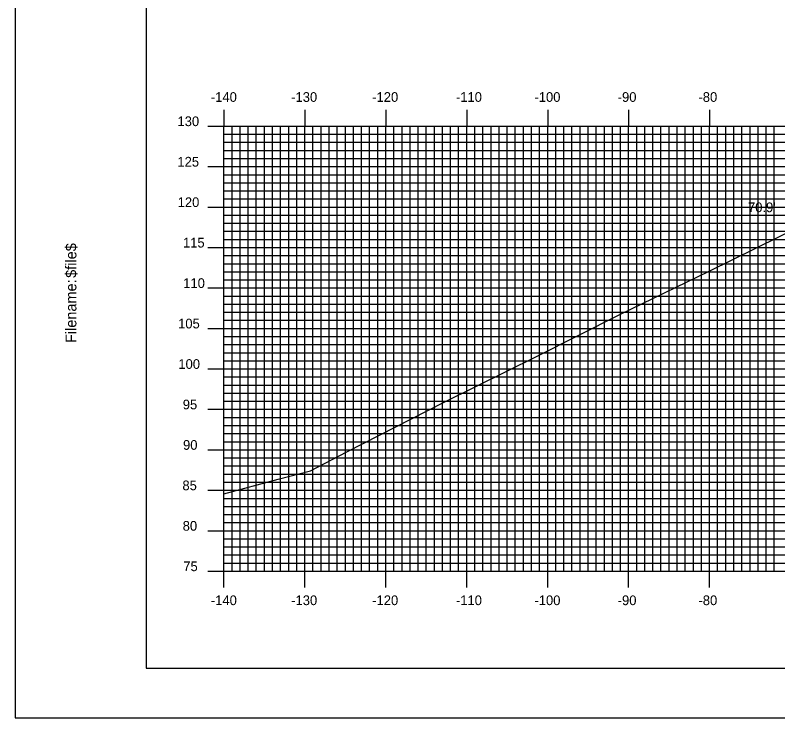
# Model space of a CAD drawing. Extents: x 1684012 to 1684355, y 461260 to 461480.
# Drawn here: x 1684011.9 to 1684106.1, y 461260 to 461346.8 of the extents above; entities that cross this region are included whole.
import ezdxf

# ---------------------------------------------------------------- set-up
doc = ezdxf.new("R2010")
doc.units = 0
for name, color, linetype in [('BORDER', 7, 'Continuous'), ('D_Text_Standard', 7, 'Continuous'), ('H_V ANNOTATION', 7, 'Continuous'), ('MAJOR', 7, 'Continuous'), ('MINOR', 7, 'Continuous'), ('PLOT BOUNDARY', 7, 'Continuous'), ('S_Roadway_Centerline', 7, 'Continuous')]:
    doc.layers.add(name, color=color, linetype=linetype)

msp = doc.modelspace()

# ---------------------------------------------------------------- linework, layer by layer
at = {"layer": 'BORDER'}
msp.add_lwpolyline([(1684028.09, 461266.072), (1684348.09, 461266.072), (1684348.09, 461476.072), (1684028.09, 461476.072)], close=True, dxfattribs=at)
at = {"layer": 'MAJOR'}
for p, q in [((1684037.69, 461335.076), (1684037.69, 461333.072)), ((1684047.69, 461335.076), (1684047.69, 461333.072)), ((1684057.69, 461335.076), (1684057.69, 461333.072)), ((1684067.69, 461335.076), (1684067.69, 461333.072)), ((1684077.69, 461335.076), (1684077.69, 461333.072)), ((1684087.69, 461335.076), (1684087.69, 461333.072)), ((1684097.69, 461335.076), (1684097.69, 461333.072)), ((1684035.686, 461333.072), (1684037.69, 461333.072)), ((1684037.69, 461333.072), (1684317.69, 461333.072)), ((1684037.69, 461278.072), (1684037.69, 461333.072)), ((1684037.69, 461278.072), (1684037.69, 461333.072)), ((1684037.69, 461333.072), (1684317.69, 461333.072)), ((1684047.69, 461278.072), (1684047.69, 461333.072)), ((1684057.69, 461278.072), (1684057.69, 461333.072)), ((1684067.69, 461278.072), (1684067.69, 461333.072)), ((1684077.69, 461278.072), (1684077.69, 461333.072)), ((1684087.69, 461278.072), (1684087.69, 461333.072)), ((1684097.69, 461278.072), (1684097.69, 461333.072)), ((1684035.686, 461328.072), (1684037.69, 461328.072)), ((1684037.69, 461328.072), (1684317.69, 461328.072)), ((1684035.686, 461323.072), (1684037.69, 461323.072)), ((1684037.69, 461323.072), (1684317.69, 461323.072)), ((1684035.686, 461318.072), (1684037.69, 461318.072)), ((1684037.69, 461318.072), (1684317.69, 461318.072)), ((1684035.686, 461313.072), (1684037.69, 461313.072)), ((1684037.69, 461313.072), (1684317.69, 461313.072)), ((1684035.686, 461308.072), (1684037.69, 461308.072)), ((1684037.69, 461308.072), (1684317.69, 461308.072)), ((1684035.686, 461303.072), (1684037.69, 461303.072)), ((1684037.69, 461303.072), (1684317.69, 461303.072)), ((1684035.686, 461298.072), (1684037.69, 461298.072)), ((1684037.69, 461298.072), (1684317.69, 461298.072)), ((1684035.686, 461293.072), (1684037.69, 461293.072)), ((1684037.69, 461293.072), (1684317.69, 461293.072)), ((1684035.686, 461288.072), (1684037.69, 461288.072)), ((1684037.69, 461288.072), (1684317.69, 461288.072)), ((1684035.686, 461283.072), (1684037.69, 461283.072)), ((1684037.69, 461283.072), (1684317.69, 461283.072)), ((1684035.686, 461278.072), (1684037.69, 461278.072)), ((1684037.69, 461278.072), (1684317.69, 461278.072)), ((1684037.69, 461278.072), (1684317.69, 461278.072)), ((1684037.69, 461276.068), (1684037.69, 461278.072)), ((1684047.69, 461276.068), (1684047.69, 461278.072)), ((1684057.69, 461276.068), (1684057.69, 461278.072)), ((1684067.69, 461276.068), (1684067.69, 461278.072)), ((1684077.69, 461276.068), (1684077.69, 461278.072)), ((1684087.69, 461276.068), (1684087.69, 461278.072)), ((1684097.69, 461276.068), (1684097.69, 461278.072))]:
    msp.add_line(p, q, dxfattribs=at)
at = {"layer": 'MINOR'}
for p, q in [((1684038.69, 461278.072), (1684038.69, 461333.072)), ((1684039.69, 461278.072), (1684039.69, 461333.072)), ((1684040.69, 461278.072), (1684040.69, 461333.072)), ((1684041.69, 461278.072), (1684041.69, 461333.072)), ((1684042.69, 461278.072), (1684042.69, 461333.072)), ((1684043.69, 461278.072), (1684043.69, 461333.072)), ((1684044.69, 461278.072), (1684044.69, 461333.072)), ((1684045.69, 461278.072), (1684045.69, 461333.072)), ((1684046.69, 461278.072), (1684046.69, 461333.072)), ((1684048.69, 461278.072), (1684048.69, 461333.072)), ((1684049.69, 461278.072), (1684049.69, 461333.072)), ((1684050.69, 461278.072), (1684050.69, 461333.072)), ((1684051.69, 461278.072), (1684051.69, 461333.072)), ((1684052.69, 461278.072), (1684052.69, 461333.072)), ((1684053.69, 461278.072), (1684053.69, 461333.072)), ((1684054.69, 461278.072), (1684054.69, 461333.072)), ((1684055.69, 461278.072), (1684055.69, 461333.072)), ((1684056.69, 461278.072), (1684056.69, 461333.072)), ((1684058.69, 461278.072), (1684058.69, 461333.072)), ((1684059.69, 461278.072), (1684059.69, 461333.072)), ((1684060.69, 461278.072), (1684060.69, 461333.072)), ((1684061.69, 461278.072), (1684061.69, 461333.072)), ((1684062.69, 461278.072), (1684062.69, 461333.072)), ((1684063.69, 461278.072), (1684063.69, 461333.072)), ((1684064.69, 461278.072), (1684064.69, 461333.072)), ((1684065.69, 461278.072), (1684065.69, 461333.072)), ((1684066.69, 461278.072), (1684066.69, 461333.072)), ((1684068.69, 461278.072), (1684068.69, 461333.072)), ((1684069.69, 461278.072), (1684069.69, 461333.072)), ((1684070.69, 461278.072), (1684070.69, 461333.072)), ((1684071.69, 461278.072), (1684071.69, 461333.072)), ((1684072.69, 461278.072), (1684072.69, 461333.072)), ((1684073.69, 461278.072), (1684073.69, 461333.072)), ((1684074.69, 461278.072), (1684074.69, 461333.072)), ((1684075.69, 461278.072), (1684075.69, 461333.072)), ((1684076.69, 461278.072), (1684076.69, 461333.072)), ((1684078.69, 461278.072), (1684078.69, 461333.072)), ((1684079.69, 461278.072), (1684079.69, 461333.072)), ((1684080.69, 461278.072), (1684080.69, 461333.072)), ((1684081.69, 461278.072), (1684081.69, 461333.072)), ((1684082.69, 461278.072), (1684082.69, 461333.072)), ((1684083.69, 461278.072), (1684083.69, 461333.072)), ((1684084.69, 461278.072), (1684084.69, 461333.072)), ((1684085.69, 461278.072), (1684085.69, 461333.072)), ((1684086.69, 461278.072), (1684086.69, 461333.072)), ((1684088.69, 461278.072), (1684088.69, 461333.072)), ((1684089.69, 461278.072), (1684089.69, 461333.072)), ((1684090.69, 461278.072), (1684090.69, 461333.072)), ((1684091.69, 461278.072), (1684091.69, 461333.072)), ((1684092.69, 461278.072), (1684092.69, 461333.072)), ((1684093.69, 461278.072), (1684093.69, 461333.072)), ((1684094.69, 461278.072), (1684094.69, 461333.072)), ((1684095.69, 461278.072), (1684095.69, 461333.072)), ((1684096.69, 461278.072), (1684096.69, 461333.072)), ((1684098.69, 461278.072), (1684098.69, 461333.072)), ((1684099.69, 461278.072), (1684099.69, 461333.072)), ((1684100.69, 461278.072), (1684100.69, 461333.072)), ((1684101.69, 461278.072), (1684101.69, 461333.072)), ((1684102.69, 461278.072), (1684102.69, 461333.072)), ((1684103.69, 461278.072), (1684103.69, 461333.072)), ((1684104.69, 461278.072), (1684104.69, 461333.072)), ((1684105.69, 461278.072), (1684105.69, 461333.072)), ((1684037.69, 461332.072), (1684317.69, 461332.072)), ((1684037.69, 461332.072), (1684039.694, 461332.072)), ((1684037.69, 461331.072), (1684317.69, 461331.072)), ((1684037.69, 461331.072), (1684039.694, 461331.072)), ((1684037.69, 461330.072), (1684317.69, 461330.072)), ((1684037.69, 461330.072), (1684039.694, 461330.072)), ((1684037.69, 461329.072), (1684317.69, 461329.072)), ((1684037.69, 461329.072), (1684039.694, 461329.072)), ((1684037.69, 461327.072), (1684317.69, 461327.072)), ((1684037.69, 461327.072), (1684039.694, 461327.072)), ((1684037.69, 461326.072), (1684317.69, 461326.072)), ((1684037.69, 461326.072), (1684039.694, 461326.072)), ((1684037.69, 461325.072), (1684317.69, 461325.072)), ((1684037.69, 461325.072), (1684039.694, 461325.072)), ((1684037.69, 461324.072), (1684317.69, 461324.072)), ((1684037.69, 461324.072), (1684039.694, 461324.072)), ((1684037.69, 461322.072), (1684317.69, 461322.072)), ((1684037.69, 461322.072), (1684039.694, 461322.072)), ((1684037.69, 461321.072), (1684037.69, 461321.072)), ((1684037.69, 461321.072), (1684039.694, 461321.072)), ((1684037.69, 461321.072), (1684317.69, 461321.072)), ((1684037.69, 461320.072), (1684317.69, 461320.072)), ((1684037.69, 461320.072), (1684039.694, 461320.072)), ((1684037.69, 461319.072), (1684317.69, 461319.072)), ((1684037.69, 461319.072), (1684039.694, 461319.072)), ((1684037.69, 461317.072), (1684317.69, 461317.072)), ((1684037.69, 461317.072), (1684039.694, 461317.072)), ((1684037.69, 461316.072), (1684317.69, 461316.072)), ((1684037.69, 461316.072), (1684039.694, 461316.072)), ((1684037.69, 461315.072), (1684317.69, 461315.072)), ((1684037.69, 461315.072), (1684039.694, 461315.072)), ((1684037.69, 461314.072), (1684317.69, 461314.072)), ((1684037.69, 461314.072), (1684039.694, 461314.072)), ((1684037.69, 461312.072), (1684317.69, 461312.072)), ((1684037.69, 461312.072), (1684039.694, 461312.072)), ((1684037.69, 461311.072), (1684317.69, 461311.072)), ((1684037.69, 461311.072), (1684039.694, 461311.072)), ((1684037.69, 461310.072), (1684317.69, 461310.072)), ((1684037.69, 461310.072), (1684039.694, 461310.072)), ((1684037.69, 461309.072), (1684317.69, 461309.072)), ((1684037.69, 461309.072), (1684039.694, 461309.072)), ((1684037.69, 461307.072), (1684317.69, 461307.072)), ((1684037.69, 461307.072), (1684039.694, 461307.072)), ((1684037.69, 461306.072), (1684317.69, 461306.072)), ((1684037.69, 461306.072), (1684039.694, 461306.072)), ((1684037.69, 461305.072), (1684317.69, 461305.072)), ((1684037.69, 461305.072), (1684039.694, 461305.072)), ((1684037.69, 461304.072), (1684317.69, 461304.072)), ((1684037.69, 461304.072), (1684039.694, 461304.072)), ((1684037.69, 461302.072), (1684317.69, 461302.072)), ((1684037.69, 461302.072), (1684039.694, 461302.072)), ((1684037.69, 461301.072), (1684317.69, 461301.072)), ((1684037.69, 461301.072), (1684039.694, 461301.072)), ((1684037.69, 461300.072), (1684317.69, 461300.072)), ((1684037.69, 461300.072), (1684039.694, 461300.072)), ((1684037.69, 461299.072), (1684317.69, 461299.072)), ((1684037.69, 461299.072), (1684039.694, 461299.072)), ((1684037.69, 461297.072), (1684317.69, 461297.072)), ((1684037.69, 461297.072), (1684039.694, 461297.072)), ((1684037.69, 461296.072), (1684317.69, 461296.072)), ((1684037.69, 461296.072), (1684039.694, 461296.072)), ((1684037.69, 461295.072), (1684317.69, 461295.072)), ((1684037.69, 461295.072), (1684039.694, 461295.072)), ((1684037.69, 461294.072), (1684317.69, 461294.072)), ((1684037.69, 461294.072), (1684039.694, 461294.072)), ((1684037.69, 461292.072), (1684317.69, 461292.072)), ((1684037.69, 461292.072), (1684039.694, 461292.072)), ((1684037.69, 461291.072), (1684317.69, 461291.072)), ((1684037.69, 461291.072), (1684039.694, 461291.072)), ((1684037.69, 461290.072), (1684317.69, 461290.072)), ((1684037.69, 461290.072), (1684039.694, 461290.072)), ((1684037.69, 461289.072), (1684317.69, 461289.072)), ((1684037.69, 461289.072), (1684039.694, 461289.072)), ((1684037.69, 461287.072), (1684317.69, 461287.072)), ((1684037.69, 461287.072), (1684039.694, 461287.072)), ((1684037.69, 461286.072), (1684317.69, 461286.072)), ((1684037.69, 461286.072), (1684039.694, 461286.072)), ((1684037.69, 461285.072), (1684317.69, 461285.072)), ((1684037.69, 461285.072), (1684039.694, 461285.072)), ((1684037.69, 461284.072), (1684317.69, 461284.072)), ((1684037.69, 461284.072), (1684039.694, 461284.072)), ((1684037.69, 461282.072), (1684317.69, 461282.072)), ((1684037.69, 461282.072), (1684039.694, 461282.072)), ((1684037.69, 461281.072), (1684317.69, 461281.072)), ((1684037.69, 461281.072), (1684039.694, 461281.072)), ((1684037.69, 461280.072), (1684317.69, 461280.072)), ((1684037.69, 461280.072), (1684039.694, 461280.072)), ((1684037.69, 461279.072), (1684317.69, 461279.072)), ((1684037.69, 461279.072), (1684039.694, 461279.072))]:
    msp.add_line(p, q, dxfattribs=at)
at = {"layer": 'PLOT BOUNDARY'}
msp.add_lwpolyline([(1684011.903, 461259.954), (1684351.903, 461259.954), (1684351.903, 461479.954), (1684011.903, 461479.954)], close=True, dxfattribs=at)
at = {"layer": 'S_Roadway_Centerline'}
msp.add_lwpolyline([(1684037.69, 461287.617), (1684044.376, 461289.427), (1684048.403, 461290.455), (1684052.854, 461292.809), (1684064.915, 461298.96), (1684076.41, 461304.658), (1684086.614, 461309.81), (1684097.624, 461315.158), (1684109.163, 461320.819)], dxfattribs=at)

# ---------------------------------------------------------------- texts
at = {"layer": 'BORDER'}
for s, p in [('$file$', (1684019.46, 461314.323)), ('Filename:', (1684019.46, 461306.269))]:
    msp.add_text(s, height=1.3392, rotation=90, dxfattribs=at).set_placement(p)
at = {"layer": 'D_Text_Standard'}
msp.add_text("70.9'", height=1.2, dxfattribs=at).set_placement((1684102.439, 461322.441))
at = {"layer": 'H_V ANNOTATION'}
for s, p in [('-140', (1684036.074, 461336.072)), ('-130', (1684045.999, 461336.072)), ('-120', (1684056.01, 461336.072)), ('-110', (1684066.352, 461336.072)), ('-100', (1684076.053, 461336.072)), ('-90', (1684086.341, 461336.072)), ('-80', (1684096.32, 461336.072)), ('130', (1684031.95, 461333.072)), ('125', (1684031.939, 461328.072)), ('120', (1684031.971, 461323.072)), ('115', (1684032.625, 461318.072)), ('110', (1684032.657, 461313.072)), ('105', (1684032.025, 461308.072)), ('100', (1684032.057, 461303.072)), ('95', (1684032.603, 461298.072)), ('90', (1684032.635, 461293.072)), ('85', (1684032.56, 461288.072)), ('80', (1684032.592, 461283.072)), ('75', (1684032.666, 461278.072)), ('-140', (1684036.074, 461273.872)), ('-130', (1684045.999, 461273.872)), ('-120', (1684056.01, 461273.872)), ('-110', (1684066.352, 461273.872)), ('-100', (1684076.053, 461273.872)), ('-90', (1684086.341, 461273.872)), ('-80', (1684096.32, 461273.872))]:
    msp.add_text(s, height=1.2, dxfattribs=at).set_placement(p)
at = {"layer": 'MAJOR'}
msp.add_text('-', height=0.012, dxfattribs=at).set_placement((1684037.681, 461278.072))

doc.saveas('drawing.dxf')
